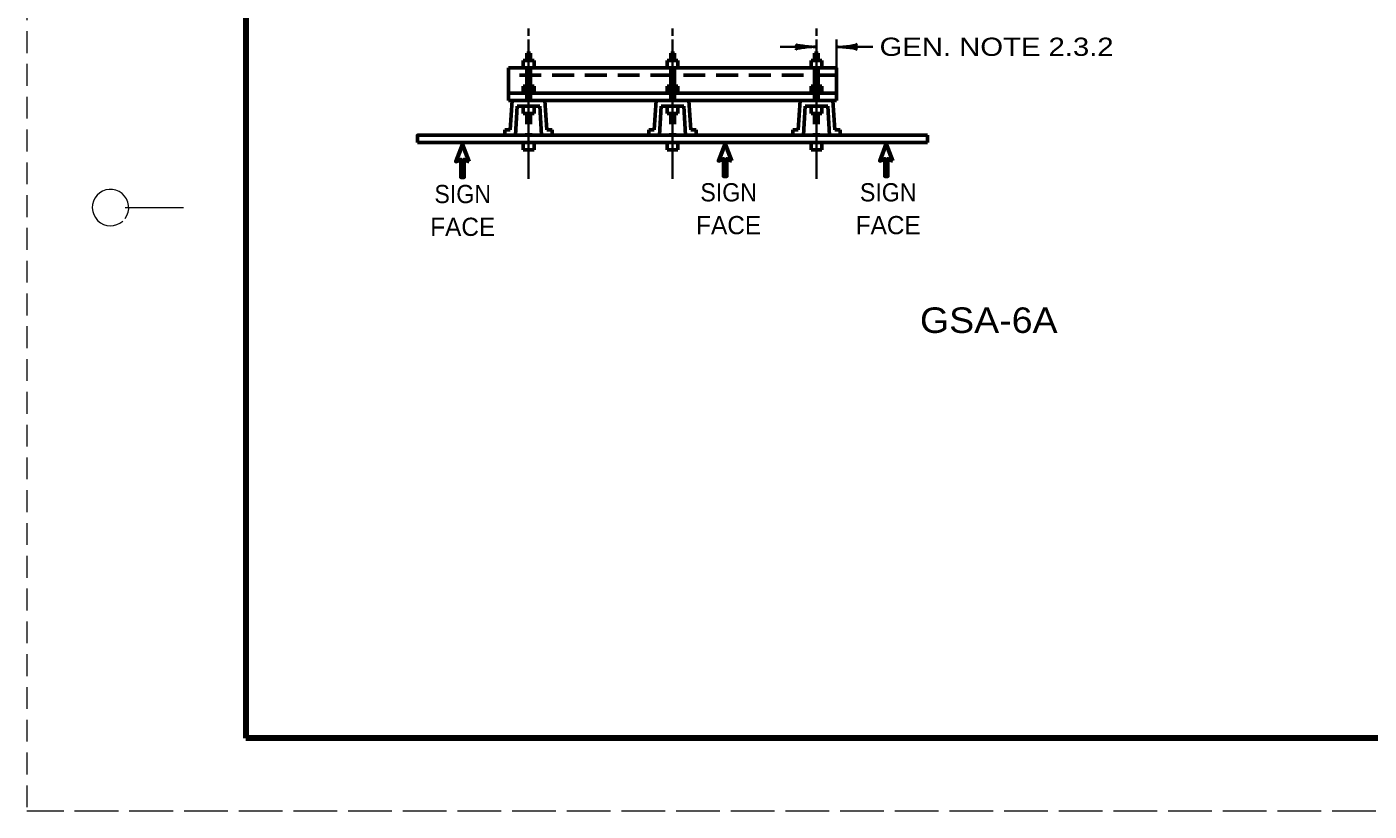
# Model space of a CAD drawing. Extents: x -45 to 635, y -382 to 59.
# Drawn here: x -44.9 to 139.3, y -381.5 to -273.9 of the extents above; entities that cross this region are included whole.
import ezdxf
from ezdxf.enums import TextEntityAlignment as Align

# ---------------------------------------------------------------- set-up
doc = ezdxf.new("R2010")
doc.units = 0
for name, pattern in [('LONG_DASHED', [7.5, 6, -1.5]), ('MEDIUM_DASHED', [4.5, 3, -1.5]), ('SHORT_DASHED', [2.7, 1.5, -1.2])]:
    doc.linetypes.add(name, pattern=pattern)
doc.layers.add('1', color=7, linetype='Continuous', lineweight=53)
doc.layers.add('61', color=7, linetype='Continuous', lineweight=35)

msp = doc.modelspace()

# ---------------------------------------------------------------- linework, layer by layer
at = {"layer": '1', "linetype": 'MEDIUM_DASHED', "lineweight": 13}
msp.add_line((-44.831, 58.54), (-44.891, -381.5), dxfattribs=at)
at = {"layer": '1', "lineweight": 35}
for p, q in [((23.937, -274.11), (23.937, -275.11)), ((43.687, -274.11), (43.687, -275.11)), ((63.437, -274.11), (63.437, -275.11)), ((23.937, -275.61), (23.937, -278.485)), ((43.687, -275.61), (43.687, -278.485)), ((63.437, -275.61), (63.437, -278.485)), ((66.177, -279.485), (66.177, -275.61)), ((58.437, -276.61), (63.437, -276.61)), ((66.177, -276.61), (71.177, -276.61)), ((23.937, -278.485), (23.937, -294.735)), ((43.687, -278.485), (43.687, -294.735)), ((63.437, -278.485), (63.437, -294.735))]:
    msp.add_line(p, q, dxfattribs=at)
at = {"layer": '1'}
for p, q in [((23.687, -277.485), (24.187, -277.485)), ((23.687, -278.485), (23.687, -277.485)), ((24.187, -278.485), (24.187, -277.485)), ((43.437, -277.485), (43.937, -277.485)), ((43.437, -278.485), (43.437, -277.485)), ((43.937, -278.485), (43.937, -277.485)), ((63.187, -277.485), (63.687, -277.485)), ((63.187, -278.485), (63.187, -277.485)), ((63.687, -278.485), (63.687, -277.485)), ((66.177, -279.485), (21.197, -279.485)), ((21.197, -279.485), (21.197, -283.985)), ((23.187, -278.485), (24.687, -278.485)), ((23.187, -278.485), (23.187, -279.485)), ((24.687, -278.485), (24.687, -279.485)), ((44.437, -278.485), (42.937, -278.485)), ((42.937, -278.485), (42.937, -279.485)), ((44.437, -278.485), (44.437, -279.485)), ((64.187, -278.485), (62.687, -278.485)), ((62.687, -278.485), (62.687, -279.485)), ((64.187, -278.485), (64.187, -279.485)), ((66.177, -279.485), (66.177, -283.985)), ((23.687, -280.985), (24.187, -280.985)), ((23.687, -281.985), (23.687, -280.985)), ((24.187, -281.985), (24.187, -280.985)), ((43.437, -280.985), (43.937, -280.985)), ((43.437, -281.985), (43.437, -280.985)), ((43.937, -281.985), (43.937, -280.985)), ((63.187, -280.985), (63.687, -280.985)), ((63.187, -281.985), (63.187, -280.985)), ((63.687, -281.985), (63.687, -280.985)), ((66.177, -282.985), (21.197, -282.985)), ((23.187, -281.985), (23.187, -282.985)), ((24.687, -281.985), (23.187, -281.985)), ((24.687, -281.985), (24.687, -282.985)), ((42.937, -281.985), (42.937, -282.985)), ((44.437, -281.985), (42.937, -281.985)), ((44.437, -281.985), (44.437, -282.985)), ((62.687, -281.985), (62.687, -282.985)), ((64.187, -281.985), (62.687, -281.985)), ((64.187, -281.985), (64.187, -282.985)), ((66.177, -283.985), (21.197, -283.985)), ((21.687, -283.985), (21.437, -287.985)), ((22.392, -284.735), (22.142, -288.735)), ((25.482, -284.735), (22.392, -284.735)), ((23.187, -285.735), (23.187, -284.735)), ((24.687, -285.735), (24.687, -284.735)), ((25.482, -284.735), (25.732, -288.735)), ((26.187, -283.985), (26.437, -287.985)), ((41.437, -283.985), (41.187, -287.985)), ((42.142, -284.735), (41.892, -288.735)), ((42.142, -284.735), (45.232, -284.735)), ((42.937, -285.735), (42.937, -284.735)), ((44.437, -285.735), (44.437, -284.735)), ((45.232, -284.735), (45.483, -288.735)), ((45.937, -283.985), (46.187, -287.985)), ((61.187, -283.985), (60.937, -287.985)), ((61.892, -284.735), (61.642, -288.735)), ((61.892, -284.735), (64.982, -284.735)), ((62.687, -285.735), (62.687, -284.735)), ((64.187, -285.735), (64.187, -284.735)), ((64.982, -284.735), (65.233, -288.735)), ((65.687, -283.985), (65.937, -287.985)), ((23.187, -285.735), (24.687, -285.735)), ((44.437, -285.735), (42.937, -285.735)), ((64.187, -285.735), (62.687, -285.735)), ((21.437, -287.985), (20.687, -287.985)), ((20.687, -287.985), (20.687, -288.735)), ((27.187, -287.985), (26.437, -287.985)), ((27.187, -287.985), (27.187, -288.735)), ((40.437, -287.985), (41.187, -287.985)), ((40.437, -287.985), (40.437, -288.735)), ((46.187, -287.985), (46.937, -287.985)), ((46.937, -287.985), (46.937, -288.735)), ((60.187, -287.985), (60.937, -287.985)), ((60.187, -287.985), (60.187, -288.735)), ((65.937, -287.985), (66.687, -287.985)), ((66.687, -287.985), (66.687, -288.735)), ((78.687, -288.735), (78.687, -289.735)), ((78.687, -289.735), (8.687, -289.735)), ((23.187, -290.735), (23.187, -289.735)), ((23.187, -290.735), (24.687, -290.735)), ((24.687, -290.735), (24.687, -289.735)), ((42.937, -290.735), (42.937, -289.735)), ((44.437, -290.735), (42.937, -290.735)), ((44.437, -290.735), (44.437, -289.735)), ((62.687, -290.735), (62.687, -289.735)), ((64.187, -290.735), (62.687, -290.735)), ((64.187, -290.735), (64.187, -289.735))]:
    msp.add_line(p, q, dxfattribs=at)
at = {"layer": '1', "linetype": 'SHORT_DASHED'}
for p, q in [((23.687, -279.485), (23.687, -283.985)), ((24.187, -279.485), (24.187, -283.985)), ((43.437, -279.485), (43.437, -283.985)), ((43.937, -279.485), (43.937, -283.985)), ((63.187, -279.485), (63.187, -283.985)), ((63.687, -279.485), (63.687, -283.985)), ((23.687, -285.735), (23.687, -288.735)), ((24.187, -285.735), (24.187, -288.735)), ((43.437, -285.735), (43.437, -288.735)), ((43.937, -285.735), (43.937, -288.735)), ((63.187, -285.735), (63.187, -288.735)), ((63.687, -285.735), (63.687, -288.735))]:
    msp.add_line(p, q, dxfattribs=at)
at = {"layer": '1', "linetype": 'MEDIUM_DASHED'}
msp.add_line((66.177, -280.485), (21.197, -280.485), dxfattribs=at)
at = {"layer": '1'}
msp.add_lwpolyline([(78.687, -288.735), (8.687, -288.735), (8.687, -289.735)], dxfattribs=at)
at = {"layer": '1', "lineweight": 60}
for points in [[(15.783, -292.356), (14.883, -289.971), (13.983, -292.356), (14.658, -292.086), (14.658, -294.471), (15.108, -294.471), (15.108, -292.086)], [(51.81, -292.24), (50.91, -289.855), (50.01, -292.24), (50.685, -291.97), (50.685, -294.355), (51.135, -294.355), (51.135, -291.97)], [(73.921, -292.24), (73.02, -289.855), (72.12, -292.24), (72.796, -291.97), (72.796, -294.355), (73.245, -294.355), (73.245, -291.97)]]:
    msp.add_lwpolyline(points, close=True, dxfattribs=at)
at = {"layer": '1', "lineweight": 40}
for centre, major_axis, ratio, start_param, end_param in [((62.316, -276.399), (1.756, -0.176), 0.07063, 3.1407148, 5.41811), ((67.268, -276.334), (-1.786, -0.156), 0.122415, 0.8963533, 3.1415927), ((67.268, -276.334), (-1.786, -0.156), 0.122415, 0.8963533, 3.1415927), ((62.346, -276.886), (1.786, 0.156), 0.122415, 0.8963533, 3.1415927), ((67.298, -276.822), (-1.756, 0.176), 0.07063, 3.1407148, 5.41811), ((67.298, -276.822), (-1.756, 0.176), 0.07063, 3.1407148, 5.41811)]:
    msp.add_ellipse(centre, major_axis=major_axis, ratio=ratio, start_param=start_param, end_param=end_param, dxfattribs=at)
at = {"layer": '61', "lineweight": 13}
msp.add_line((-31.391, -298.66), (-23.411, -298.66), dxfattribs=at)
at = {"layer": '61', "lineweight": 158}
msp.add_line((624.229, -371.5), (-14.831, -371.48), dxfattribs=at)
at = {"layer": '61', "linetype": 'LONG_DASHED', "lineweight": 13}
msp.add_line((635.169, -381.48), (-44.891, -381.5), dxfattribs=at)
at = {"layer": '61', "lineweight": 158}
msp.add_lwpolyline([(624.209, 48.54), (-14.831, 48.54), (-14.831, -371.48)], dxfattribs=at)
at = {"layer": '61', "lineweight": 13}
msp.add_arc((-33.413, -298.659), 2.5, 323.13009, 312.31439, dxfattribs=at)

# ---------------------------------------------------------------- texts
at = {"layer": '1'}
for s, height, width, p in [('GEN. NOTE 2.3.2', 2.5, 1.2, (88.146, -277.844)), ('SIGN', 2.5, 0.95, (14.904, -298.054)), ('SIGN', 2.5, 0.95, (51.389, -297.819)), ('SIGN', 2.5, 0.95, (73.281, -297.819)), ('GSA-6A', 3.5, 1.1, (87.074, -315.868))]:
    msp.add_text(s, height=height, dxfattribs=dict(at, width=width)).set_placement(p, align=Align.CENTER)
for p in [(14.904, -302.554), (51.389, -302.319), (73.28, -302.319)]:
    msp.add_text('FACE', height=2.5, dxfattribs=at).set_placement(p, align=Align.CENTER)

doc.saveas('drawing.dxf')
